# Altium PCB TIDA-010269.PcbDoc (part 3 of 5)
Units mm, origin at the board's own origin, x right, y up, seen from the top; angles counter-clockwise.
Board outline 87.61 x 53.51 mm, 8 copper layers (Top Layer, GND1, Signal 1, Power 1, Power 2, Signal 2, Layer 1, Bottom Layer), stack 1.645 mm thick; 482 components, 227 nets, 1562 pads, 953 vias.
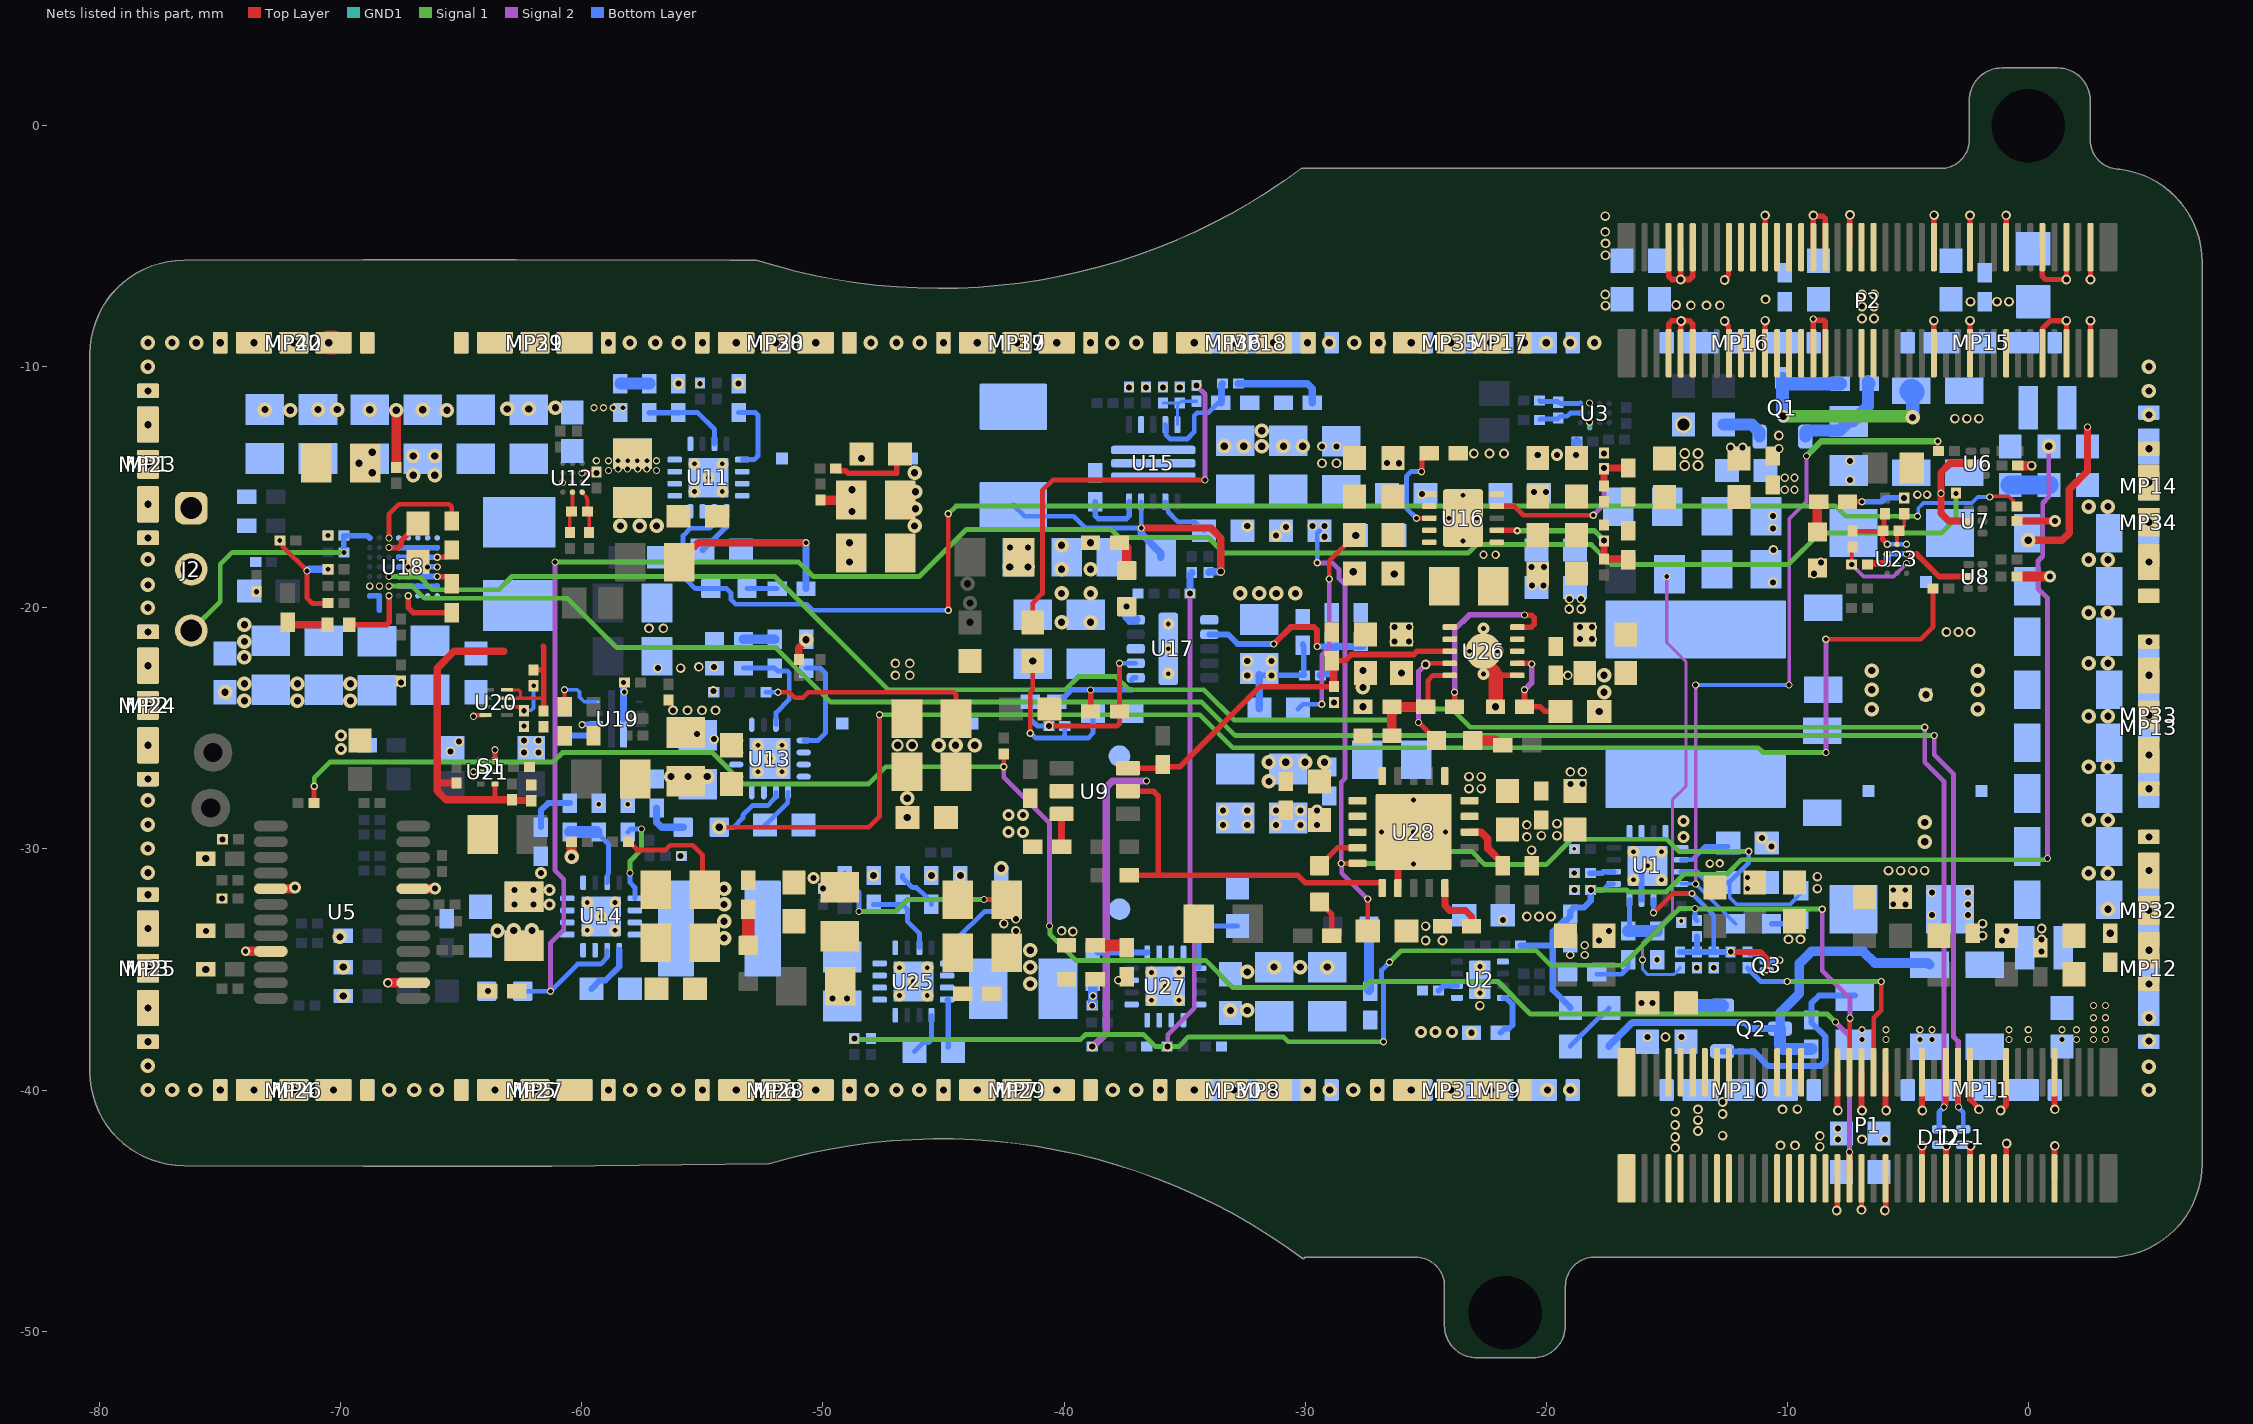
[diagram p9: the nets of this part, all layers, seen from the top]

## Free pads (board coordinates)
  round 0.5 hole 0.2: 3(-52.7,-26.8) 3(-52.7,-25.7) 3(-51.7,-26.8) 3(-51.7,-25.7)
  round 0.6 hole 0.3: 8(-67,-13.7) 8(-43.9,-20.6) 9(-66.1,-13.7) 9(-43.9,-19.8) 10(-69.25,-14) 10(-67,-14.5) 10(-44,-19) 11(-66.1,-14.5)
  round 0.4 hole 0.25: 11(-16.05,-36.4) 11(-15.8,-37.8) 11(-15.6,-36.4) 12(-15.05,-37.8)
  round 2.159 hole 3.048 unplated mask+0.127: MH2(-21.705,-49.233) MH2(0,0)

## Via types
v1: diameter 0.6, hole 0.3, Top Layer to Bottom Layer, tented both sides, 264 vias
v2: diameter 0.4, hole 0.25, Top Layer to Bottom Layer, tented both sides, 251 vias
v3: diameter 0.3, hole 0.2, Top Layer to Bottom Layer, tented both sides, 153 vias
v4: diameter 0.3, hole 0.2, Top Layer to Bottom Layer, 95 vias
v5: diameter 0.5, hole 0.25, Top Layer to Bottom Layer, tented both sides, 67 vias
v6: diameter 0.5, hole 0.2, Top Layer to Bottom Layer, 44 vias
v7: diameter 0.35, hole 0.22, Top Layer to Bottom Layer, tented both sides, 34 vias
v8: diameter 0.45, hole 0.3, Top Layer to Bottom Layer, tented both sides, 8 vias
v9: diameter 0.3, hole 0.15, Top Layer to Bottom Layer, tented both sides, 8 vias
v10: diameter 0.5, hole 0.3, Top Layer to Bottom Layer, tented both sides, 7 vias
v11: diameter 0.35, hole 0.25, Top Layer to Bottom Layer, tented both sides, 5 vias
v12: diameter 0.38, hole 0.25, Top Layer to Bottom Layer, tented both sides, 3 vias
v13: diameter 0.4, hole 0.22, Top Layer to Bottom Layer, tented both sides, 3 vias
v14: diameter 0.4, hole 0.25, Top Layer to Bottom Layer, 3 vias
v15: diameter 0.35, hole 0.2, Top Layer to Bottom Layer, tented both sides, 2 vias
v16: diameter 0.7, hole 0.5, Top Layer to Bottom Layer, tented both sides, 1 vias
v17: diameter 0.32, hole 0.21, Top Layer to Bottom Layer, tented both sides, 1 vias
v18: diameter 0.6, hole 0.3, Top Layer to Bottom Layer, 1 vias
v19: diameter 0.45, hole 0.25, Top Layer to Bottom Layer, tented both sides, 1 vias
v20: diameter 0.36, hole 0.25, Top Layer to Bottom Layer, tented both sides, 1 vias
v21: diameter 0.5, hole 0.25, Top Layer to Bottom Layer, 1 vias

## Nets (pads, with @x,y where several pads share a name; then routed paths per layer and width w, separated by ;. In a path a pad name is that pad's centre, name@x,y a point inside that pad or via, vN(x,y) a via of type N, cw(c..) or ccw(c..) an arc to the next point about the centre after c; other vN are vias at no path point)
1.8V_EN: R9.1 R166.1 R184.2 U9.6 U26.3 | length 16
  Top Layer w0.23: U9.6@-37.35,-26.65 -35.95,-26.65 -35.9,-26.6 -35.2,-26.6 -31.87,-23.27 R184.2@-28.8,-23.27 ; R166.1@-28.9,-22.2 -28.35,-22.2 -28.085,-21.935 -25.485,-21.935 -25.35,-21.8 U26.3@-24,-21.8
  Top Layer w0.3: R166.1@-28.81,-22.29 -28.81,-23.26 R184.2@-28.8,-23.27
1.15V_EN: R62.1 U9.5 U28.11 | length 15.5
  Top Layer w0.23: U9.5@-37.35,-27.6 -36.3,-27.6 -36.1,-27.8 -36.1,-31.1 ; R62.1@-37.3,-31.1 -36.1,-31.1 ; U28.11@-26.8,-31.625 -26.8,-31.44 -26.84,-31.4 -30,-31.4 -30.3,-31.1 -36.1,-31.1
1V2_DVDD: C204.1 L27.2 P1.19 P1.21
1V8_DVDD: C25.1 C183.1 L22.2 P1.47 P1.49 P1.68 P1.70 P2.51 P2.52 P2.53 P2.54 P2.55 P2.56 P2.59 P2.60 P2.61 P2.62
  other v2: -8.65,-42.35 -8.65,-41.9 -13.7,-41.7 -13.7,-41.25 -13.7,-40.8 -9.95,-33.75 -9.45,-33.75
  other v8: -14.25,-14.1 -13.7,-14.1 -14.25,-13.6 -13.7,-13.6
3.3V_AVDD: R138.1 R139.1 R143.1 R144.1 | length 4.7
  Top Layer w0.2: v3(-72.53,-17.2) -72.51,-17.2 -72.4,-17.31 -72.4,-17.465 v3(-71.4,-18.465) -71.4,-19.6 -71.181,-19.819 -70.549,-19.819 R143.1@-70.53,-19.8
  Bottom Layer w0.3: v3(-71.4,-18.465) -71.335,-18.4 v4(-70.53,-18.4)
+3.3V: C32.2 U2.6 | length 0.9
  Bottom Layer w0.24: C32.2@-24.47,-35.875 -24.45,-35.875 -24.25,-35.675 U2.6@-23.7,-35.675
+5.3V: C12.1 C98.1 C99.1 C100.1 C101.1 C201.1 R3.1 R10.1 R93.1 R95.2 R104.1 U1.3 U15.8@-36.3,-14.55 U28.10 | length 61.2
  Top Layer w0.2: R104.1@-41.3,-20.6 -41.3,-19.8 -40.9,-19.4 -40.9,-15.129 -40.471,-14.7 v3(-34.15,-14.7) ; v3(-28.5,-30.6) U28.10@-27.825,-30.6 ; C201.1@-27.4,-33.4 v3(-27.4,-32.082)
  Signal 2 w0.2: v2(-34.5,-10.77) -34.5,-10.8 -34.15,-11.15 v3(-34.15,-14.7) ; v3(-29.5,-18.13) -29.496,-18.134 -28.866,-18.134 -28.6,-18.4 -28.6,-18.778 -28.35,-19.028 -28.35,-27.083 -28.5,-27.233 v3(-28.5,-30.6) ; v3@-28.482,-30.618 -28.482,-31 v3(-27.4,-32.082)
  Signal 1 w0.2: v3(-28.5,-30.6) -26.7,-30.6 -26.2,-30.1 -23.09,-30.1 -22.54,-30.65 -20,-30.65 -18.95,-29.6 -15,-29.6 -14.5,-30.1 v3(-11.6,-30.1)
  Bottom Layer w0.152: v2(-34.5,-10.77) R95.2@-34.43,-10.7 ; C12.1@-12.45,-31.4 -12.387,-31.463 -12.387,-32.013 -12.1,-32.3 -9.89,-32.3 -9.42,-31.83 R10.1@-9.42,-31.73
  Bottom Layer w0.2: v3(-29.5,-18.13) -29.5,-16.9 C98.1@-29.4,-16.8 ; C12.1@-12.45,-31.4 -12.425,-31.4 -11.6,-30.575 v3(-11.6,-30.1)
  Bottom Layer w0.22: U1.3@-14.4,-30.95 -13.75,-30.95 -13.3,-31.4 C12.1@-12.45,-31.4
  other v2: -29.2,-17.05 -29.7,-16.6 -29.2,-16.6
AVDD_1P2: C191.1 L25.2 P2.39 P2.40 P2.41 P2.42
  other v2: -10.35,-13.4 -12.35,-13.35 -11.85,-13.35 -10.35,-12.85 -6.9,-8 -6.4,-8 -6.9,-7.5 -6.4,-7.5 -6.9,-7 -6.4,-7
DC_DC_CLK1: P1.43 R37.2 R111.1 | length 80.2
  Top Layer w0.2: R37.2@-71.12,-28.1 -71.11,-28.09 -71.11,-27.41 v3(-71.1,-27.4) ; v3(-42.5,-26.59) R111.1@-42.5,-26.06
  Top Layer w0.24: P1.43@-7.421,-43.664 v3(-7.421,-42.568)
  Signal 2 w0.2: v3(-42.5,-26.59) -42.5,-27.034 -40.6,-28.934 v3(-40.6,-33.2) ; v3(-8,-37.181) -7.421,-37.76 v3(-7.421,-42.568)
  Signal 1 w0.2: v3(-71.1,-27.4) -71.1,-27.05 -70.45,-26.4 -61.2,-26.4 -60.8,-26 -54.6,-26 -53.3,-27.3 -48.108,-27.3 -47.398,-26.59 v3(-42.5,-26.59) ; v3(-40.6,-33.2) -40.581,-33.219 -40.581,-33.556 -39.511,-34.625 -34.125,-34.625 -33,-35.75 -27.575,-35.75 -27.325,-35.5 -22,-35.5 -20.65,-36.85 -8.331,-36.85 v3(-8,-37.181)
DM_USB: D12.1 P1.28 U18.F3 | length 86.1
  Top Layer w0.23: v4(-3.5,-40.7) -3.5,-40.681 -3.428,-40.609 -3.428,-39.271 P1.28@-3.421,-39.264
  Signal 2 w0.2: v3(-4.3,-24.95) -4.3,-26.4 -3.5,-27.2 v4(-3.5,-40.7)
  Signal 1 w0.2: v3(-68,-18.7) -67.375,-18.7 -66.75,-18.7 -66.2,-19.25 -63.45,-19.25 -62.9,-18.7 -52,-18.7 -47.3,-23.4 -39.95,-23.4 -39.4,-22.85 -37.85,-22.85 -37.3,-23.4 -34.2,-23.4 -32.95,-24.65 -26.55,-24.65 -26.1,-24.2 -23.9,-24.2 -23.15,-24.95 v3(-4.3,-24.95)
  Bottom Layer w0.23: D12.1@-3.7,-41.625 -3.7,-40.919 -3.5,-40.719 v4(-3.5,-40.7)
DP_USB: D11.1 P1.26 U18.F2 | length 84.9
  Top Layer w0.23: v4@-2.921,-40.679 P1.26@-2.921,-39.264
  Signal 2 w0.2: v3(-3.9,-25.3) -3.9,-26.1 -3.1,-26.9 -3.1,-37.8 -2.9,-38
  Signal 2 w0.23: v4(-2.9,-40.7) -2.9,-38
  Signal 1 w0.2: v3(-68,-19.1) -67.034,-19.1 -66.534,-19.6 -60.6,-19.6 -58.55,-21.65 -51.95,-21.65 -49.7,-23.9 -34.3,-23.9 -32.9,-25.3 v3(-3.9,-25.3)
  Bottom Layer w0.2: v4(-2.9,-40.7) -2.9,-40.727 -2.7,-40.927 D11.1@-2.7,-41.625
  Bottom Layer w0.23: v4@-2.921,-40.679 v4(-2.9,-40.7)
FPGA_PG_1V: D5.2 R60.1 U13.14 | length 65
  Top Layer w0.2: v1(-54.3,-29.1) -48.1,-29.1 -47.657,-28.657 v3(-47.657,-24.432) ; v3(-8.4,-21.3) -4.463,-21.3 -3.96,-20.797 R60.1@-3.96,-19.2
  Signal 2 w0.2: v3(-8.4,-26) v3(-8.4,-21.3)
  Signal 1 w0.2: v3(-47.657,-24.432) -34.368,-24.432 -33,-25.8 -11.2,-25.8 -11,-26 v3(-8.4,-26)
  Bottom Layer w0.2: v1(-54.3,-29.1) -53.709,-29.1 -53.32,-28.711 -53.32,-28.591 -52.931,-28.202 -52.299,-28.202 -52.08,-27.983 -52.08,-27.971 -51.95,-27.841 U13.14@-51.95,-27.65
FPGA_PG_1V8: D6.2 R43.1 U14.14 | length 84.5
  Top Layer w0.2: v3(-3,-15.25) R43.1@-3,-15.23
  Signal 2 w0.2: v3(-61.3,-35.9) -61.3,-33.898 -60.75,-33.348 -60.75,-31.25 -61.119,-30.881 v3(-61.119,-18.1)
  Signal 1 w0.2: v3(-61.119,-18.1) -51.005,-18.1 -50.405,-18.7 -46,-18.7 -44.05,-16.75 -38.047,-16.75 -37.715,-17.082 -34.018,-17.082 -33.37,-17.73 -23.243,-17.73 -22.888,-17.375 -18.125,-17.375 -17.3,-18.2 -9.95,-18.2 -8.65,-16.9 -3.616,-16.9 -3,-16.284 v3(-3,-15.25)
  Bottom Layer w0.2: D6.2@-62.45,-35.9 v3(-61.3,-35.9) -60.177,-34.777 -59.227,-34.777 -58.95,-34.5 U14.14@-58.95,-34.2
FPGA_PG_2V5: D4.2 R54.1 U11.14 | length 64.9
  Top Layer w0.15: v3(-1.6,-15.4) -1.559,-15.4 -1.524,-15.365 -0.807,-15.365 -0.625,-15.547 -0.625,-15.665 -0.49,-15.8 R54.1@-0.47,-15.8
  Top Layer w0.2: v3(-44.8,-20.1) v3(-44.8,-16.1)
  Signal 1 w0.2: v3(-44.8,-16.1) -44.48,-15.78 -23.818,-15.78 -23.768,-15.83 -23.133,-15.83 -23.082,-15.78 -7.99,-15.78 -7.57,-16.2 v3(-4.6,-16.2)
  Bottom Layer w0.15: v3(-4.6,-16.2) -4.571,-16.171 -4.571,-15.874 -4.348,-15.65 -2.35,-15.65 -2.1,-15.4 v3(-1.6,-15.4)
  Bottom Layer w0.2: U11.14@-54.5,-16 -54.5,-16.5 -54.7,-16.7 -55.5,-16.7 -55.8,-17 -55.8,-18.7 -55.3,-19.2 D4.2@-54.65,-19.2 -54,-19.2 -53.813,-19.387 -53.813,-19.663 -53.625,-19.85 -50.672,-19.85 -50.422,-20.1 v3(-44.8,-20.1)
"GLOBAL ENABLE": P1.44 R8.1 R94.1 R110.1 R161.1 R173.1 | length 73.3
  Top Layer w0.2: P1.44@-7.421,-39.264 -7.41,-39.254 -7.41,-37.029 v3(-7.4,-37.019)
  Signal 2 w0.2: v2(-35.7,-38.2) -35.7,-37.7 -34.6,-36.6 -34.6,-32.964 -34.77,-32.794 v2(-34.77,-19.4) ; v3(-8.55,-32.5) -8.55,-35.05 -7.4,-36.2 v3(-7.4,-37.019)
  Signal 1 w0.2: v2(-48.7,-37.87) -48.67,-37.9 -39.31,-37.9 -39.11,-37.7 -36.7,-37.7 -36.2,-38.2 v2(-35.7,-38.2) -35.24,-38.2 -34.84,-37.8 -30.909,-37.8 -30.709,-38 v3(-26.75,-38) ; v2@-34.785,-19.415 v2(-34.77,-19.4) ; v3(-26.5,-34.7) -26.023,-34.223 -20.41,-34.223 -19.808,-34.825 -16.825,-34.825 -14.472,-32.472 v3(-13.822,-32.472) ; v3@-13.776,-32.472 -13.776,-32.486 -8.564,-32.486 v3(-8.55,-32.5)
  Bottom Layer w0.2: v3(-26.75,-38) -26.75,-35.467 -26.827,-35.391 -26.827,-35.027 v3(-26.5,-34.7) ; v3(-13.822,-32.472) -13.822,-32.898 R8.1@-13.75,-32.97
  Bottom Layer w0.3: v2(-34.77,-19.4) -34.77,-18.62 -34.7,-18.55 R94.1@-34.7,-18.53
GND: C13.2 C16.2 C17.1 C24.2 C25.2 C32.1 C33.2 C34.2 C39.2 C40.2 C41.2 C42.2 C43.2 C47.2 C50.2 C51.2 C52.2 C53.2 C54.2 C55.2 C57.2 C58.2 C59.2 C60.2 C61.2 C62.2 C63.2 C64.2 C65.2 C67.2 C68.2 C72.2 C73.2 C74.2 C75.2 C76.2 C77.2 C78.2 C79.2 C80.2 C81.2 C82.2 C83.1 C84.2 C85.2 C86.2 C87.2 C88.2 C90.2 C91.2 C92.2 C95.2 C96.2 C97.2 C98.2 C99.2 C100.2 C101.2 C102.2 C103.2 C104.2 C106.2 C107.2 C108.2 C109.2 C110.2 C113.2 C114.2 C115.1 C116.1 C117.2 C118.2 C119.1 C120.2 C121.2 C123.1 C125.2 C126.2 C127.2 C128.2 C129.2 C130.2 C131.2 C132.2 C133.2 C135.2 C136.2 C137.2 C138.2 C139.2 C140.2 C141.2 C142.2 C143.2 C144.2 C145.2 C146.2 C148.2 C149.1 C150.2 C151.2 C152.1 C153.1 C154.2 C155.2 C169.2 C172.2 C173.2 C174.2 C175.2 C176.2 C177.2 C178.2 C179.2 C180.2 C181.2 C182.2 C183.2 C184.2 C185.2 C186.2 C187.2 C190.2 C191.2 C192.2 C193.2 C194.2 C195.2 C196.2 C197.2 C198.2 C199.2 C200.2 C201.2 C202.2 C203.2 C204.2 C205.2 C206.2 C207.2 D8.1 D10.2 D11.2 D12.2 J2.2 L20.1 L21.1 L24.1 L28.1 L29.1 MP1.1 MP2.1 MP3.1 MP4.1 MP5.1 MP6.1 MP7.1 MP8.1 MP9.1 MP10.1 MP11.1 MP12.1 MP13.1 MP14.1 MP15.1 MP16.1 MP17.1 MP18.1 MP19.1 MP20.1 MP21.1 MP22.1 MP23.1 MP24.1 MP25.1 MP26.1 MP27.1 MP28.1 MP29.1 MP30.1 MP31.1 MP32.1 MP33.1 MP34.1 MP35.1 MP36.1 MP37.1 MP38.1 MP39.1 MP40.1 P1.9 P1.10 P1.17 P1.18 P1.23 P1.24 P1.27 P1.31 P1.32 P1.37 P1.38 P1.41 P1.42 P1.45 P1.46 P1.51 P1.52 P1.53 P1.54 P1.55 P1.56 P1.63 P1.64 P1.65 P1.66 P1.71 P1.72 P1.73 P1.74 P2.3 P2.4 P2.7 P2.8 P2.11 P2.12 P2.17 P2.18 P2.23 P2.24 P2.29 P2.30 P2.44 P2.47 P2.48 P2.49 P2.50 P2.57 P2.58 P2.63 P2.64 P2.69 P2.70 P2.71 P2.72 P2.73 P2.74 pad.3 pad.11@-15.6,-36.4 pad.11@-16.05,-36.4 R48.2 R49.2 R74.1 R75.2 R85.1 R86.2 R87.1 R88.2 R96.1 R97.1 R98.1 R100.1 R107.2 R126.2 R127.2 R129.1 R130.2 R132.1 R135.2 R137.1 R140.1 R141.1 R142.1 R151.2 R168.1 R169.2 R170.1 R180.1 R181.2 R182.1 R184.1 R185.1 R194.1 R195.1 S1.1 S1.3 U2.1 U2.5 U2.9 U3.C1 U3.C3 U5.5 U5.9 U5.14 U5.20 U6.2 U7.2 U8.2 U9.2 U11.3 U11.4 U11.5 U11.17@-54.75,-14.6 U12.B3 U12.C1 U13.3 U13.4 U13.5 U13.17 U14.3 U14.4 U14.5 U14.17@-59.2,-32.8 U15.2 U15.6@-36.3,-13.45 U16.4 U16.11 U17.6 U18.A4 U18.B4 U18.C4 U18.D4 U18.E4 U18.G2 U18.H2 U19.8 U20.4 U21.2 U21.6 U23.B3 U23.C1 U23.C3 U25.3 U25.4 U25.5 U25.17@-46.25,-35.5 U26.6 U26.11 U27.3 U27.4 U27.5 U27.17@-35.8,-35.7 U28.12 U28.21 | length 95.5
  Top Layer w0.102: C169.2@-18.5,-22.8 C169.2@-18.4,-22.7
  Top Layer w0.127: C61.2@-59.43,-14.4 -59.415,-14.385 C61.2@-59.4,-14.37
  Top Layer w0.18: v3(-64.5,-24.5) -64.45,-24.45 U20.4@-64,-24.45
  Top Layer w0.2: v3(-64.5,-26.8) U21.2@-64.2,-26.8 ; U21.6@-63.6,-26.3 v3(-63.6,-25.89) ; v1@-50.7,-21.36 v1(-50.7,-21.325) ; U28.21@-26.15,-29.95 v6(-25.5,-29.3)
  Top Layer w0.22: v2(-68.05,-35.555) v2@-68.047,-35.553 ; U5.14@-67.003,-35.553 U5.14@-67,-35.55 ; U12.B3@-59.99,-14.4 C61.2@-59.43,-14.4 ; v2(-12.6,-8.1) -12.6,-8.149 -12.436,-8.313 -12.436,-9.423 P2.63@-12.421,-9.438 ; v2(-12.6,-6.4) -12.6,-6.351 -12.436,-6.187 -12.436,-5.053 P2.64@-12.421,-5.038 ; P2.57@-10.921,-9.438 v2(-10.921,-8.088) ; P2.58@-10.921,-5.038 v2(-10.921,-3.721) v2@-10.9,-3.7 ; P2.50@-8.921,-5.038 v2(-8.921,-3.721) -8.886,-3.755 -8.515,-3.755 -8.421,-3.85 P2.48@-8.421,-5.038 ; v2(-7.95,-45) -7.921,-44.971 P1.45@-7.921,-43.664 ; P2.44@-7.421,-5.038 -7.408,-5.025 -7.408,-3.708 v2(-7.4,-3.7) ; v2@-6.95,-45 v2(-6.921,-44.971) P1.41@-6.921,-43.664 ; v2(-5.95,-45) -5.921,-44.971 P1.37@-5.921,-43.664 ; P1.32@-4.421,-39.264 P1.32@-4.41,-39.274 ; P2.29@-3.921,-9.438 v2(-3.921,-8.088) ; P2.30@-3.921,-5.038 -3.921,-3.721 v2@-3.9,-3.7 ; P1.24@-2.421,-39.264 -2.406,-39.279 -2.406,-40.406 -2.05,-40.762 v2(-2.05,-40.8) ; P2.23@-2.421,-9.438 v2(-2.421,-8.088) ; P2.24@-2.421,-5.038 v2(-2.421,-3.721) v2@-2.4,-3.7 ; P2.18@-0.921,-5.038 v2(-0.921,-3.721) v2@-0.9,-3.7 ; P2.12@0.579,-5.038 0.579,-6.25 0.708,-6.379 v2(1.579,-6.379) P2.8@1.579,-5.038 ; P2.7@1.579,-9.438 v2(1.579,-8.088) ; P2.3@2.579,-9.438 v2(2.579,-8.088) ; v2(2.579,-6.379) P2.4@2.579,-5.038
  Top Layer w0.23: -22.1,-22.8 U26.6@-21.2,-22.8 ; P2.73@-14.921,-9.438 -14.921,-8.235 -14.786,-8.1 -14.055,-8.1 -13.921,-8.235 P2.69@-13.921,-9.438 ; P2.74@-14.921,-5.038 -14.921,-6.245 -14.786,-6.379 v14(-14.421,-6.379) ; P2.71@-14.421,-9.438 -14.411,-9.428 v14@-14.411,-8.111 ; P2.72@-14.421,-5.038 v14(-14.421,-6.379) ; P2.70@-13.921,-5.038 -13.921,-6.245 -14.055,-6.379 v14(-14.421,-6.379) ; P2.49@-8.921,-9.438 v4(-8.921,-8.021) -8.829,-8.071 -8.485,-8.071 -8.421,-8.135 P2.47@-8.421,-9.438 ; U23.C1@-4.939,-17.765 -4.635,-17.765 -3.7,-18.7 U8.2@-2.5,-18.7 ; P2.11@0.579,-9.438 0.589,-9.428 0.589,-8.411 0.912,-8.088 v2(1.579,-8.088)
  Top Layer w0.24: P1.17@-0.921,-43.664 v2@-0.921,-42.321
  Top Layer w0.25: P1.46@-7.921,-39.264 -7.921,-40.829 v2(-7.9,-40.85) ; P1.42@-6.921,-39.264 -6.921,-40.829 v2(-6.9,-40.85) ; P1.38@-5.921,-39.264 -5.921,-40.829 v2(-5.9,-40.85) ; P1.31@-4.421,-43.664 v2@-4.421,-42.421 ; P1.32@-4.421,-39.274 -4.421,-40.829 v2(-4.4,-40.85) ; P1.27@-3.421,-43.664 v2@-3.421,-42.421 ; P1.23@-2.421,-43.664 v2@-2.421,-42.421 ; v2(-1.15,-40.85) -1.14,-40.85 -0.921,-40.631 P1.18@-0.921,-39.264 ; P1.9@1.079,-43.664 v2@1.079,-42.421 ; P1.10@1.079,-39.264 1.079,-40.779 v2(1.1,-40.8)
  Top Layer w0.3: R88.2@-51,-22.14 -51,-21.66 v1@-50.7,-21.36 ; C64.2@-48.8,-15.4 v1(-48.8,-15.1) ; U28.12@-26.15,-31.625 U28.21@-26.15,-29.95 ; C151.2@-6.67,-18.2 -6.635,-18.165 v3(-5.85,-18.165) ; U7.2@-2.5,-16.4 -3.3,-16.4 -3.623,-16.077 v3(-3.623,-15.25) -3.623,-14.385 -3.238,-14 U6.2@-2.4,-14 ; C54.2@-0.47,-16.4 v5(1.1,-16.4)
  Top Layer w0.4: v13(-73.95,-34.25) U5.9@-72.9,-34.25 ; U5.5@-72.9,-31.65 v5@-71.95,-31.65 ; v2@-68.047,-35.553 U5.14@-67.003,-35.553 ; R126.2@-67.7,-14.17 v1(-67.7,-11.8) ; U5.20@-67,-31.65 v5(-66.1,-31.65) ; v1(-60.43,-30.33) R85.1@-60.43,-29.7 ; R74.1@-50.1,-15.53 C64.2@-48.837,-15.53 ; U26.11@-22.6,-21.8 -22.6,-22.094 -22.1,-22.594 -22.1,-22.8 ; C55.2@-0.47,-18.7 v5(0.9,-18.7) ; C53.2@-0.44,-14.1 v2(0.14,-14.1)
  Top Layer w0.5: C184.2@-17.825,-24.3 v1(-17.8,-24.3)
  Top Layer w0.6: v1(-22.1,-24.1) -22.1,-22.8
  Top Layer w1: v1(-70.498,-9) MP40.1@-70.3,-9
  GND1 w0.23: -18.2,-12.536 v3(-18.2,-12.3)
  Bottom Layer w0.23: U18.E4@-67.6,-18.3 v4(-67.2,-18.3) v3(-66.8,-18.3) v3(-66.4,-18.3) v3(-66,-18.3) ; v3(-60,-24.85) -59.981,-24.85 -59.966,-24.835 -59.429,-24.835 U19.8@-59.419,-24.825 ; v3(-5.85,-17.765) v4(-5.05,-17.765)
  Bottom Layer w0.3: v7(-38.83,-36.5) R181.2@-38.815,-36.485 ; C198.2@-38.815,-35.515 C198.2@-38.8,-35.5 ; C34.2@-18.73,-13.1 -18.72,-13.11 C34.2@-18.715,-13.115 ; v3(-5.85,-18.165) v3(-5.85,-17.765)
  Bottom Layer w0.4: R181.2@-38.815,-36.485 C198.2@-38.815,-35.515 ; v5(-18.757,-13.663) -18.744,-13.65 -18.744,-13.11 -18.72,-13.11 C34.2@-18.715,-13.11
  other v1: -78,-40 -77,-40 -76.041,-40 -75,-40 -73.6,-40 -71.95,-40 -70.3,-40 -67.994,-40 -66.95,-40 -66.022,-40 -63.6,-40 -61.95,-40 -58.9,-40 -57.991,-40 -57.005,-40 -56,-40 -55,-40 -53.6,-40 -51.95,-40 -50.3,-40 -48.9,-40 -47.978,-40 -46.95,-40 -46,-40 -45,-40 -43.6,-40 -41.95,-40 -40.3,-40 -37.976,-40 -37.005,-40 -36,-40 -34.6,-40 -32.95,-40 -31.3,-40 -29.9,-40 -28.979,-40 -28,-40 -27,-40 -25.6,-40 -23.95,-40 -22.3,-40 -19.95,-40 -19,-40 5,-40 5,-39.026 -78,-39 -78,-38 5,-37.966 5,-37 -78,-36.6 -69.9,-36.1 5,-35.6 -32.4,-35.1 -75.6,-35 -78,-34.95 -69.9,-34.9 -31.286,-34.903 -30.2,-34.9 -29.086,-34.903 5,-34.2 -70.039,-33.65 3.4,-33.5 -78,-33.3 5,-32.55 -78,-31.9 -78,-30.984 5,-30.9 -42.6,-30.8 -75.6,-30.4 -78,-29.982 5,-29.5 -78,-28.99 -46.5,-28.7 -78,-27.989 -46.5,-27.9 5,-27.5 -78,-27.1 5,-26.1 -78,-25.7 5,-24.45 -27.6,-24.1 -78,-24.05 -74,-23.85 -71.8,-23.85 -69.6,-23.85 -74.8,-23.5 -17.6,-23.5 -27.6,-23.3 -74,-23.15 -71.8,-23.15 -69.6,-23.15 -17.6,-22.8 5,-22.8 -26,-22.7 -27.6,-22.6 -78,-22.4 5,-21.4 -78,-21 -40.1,-20.6 -38.9,-20.6 -78,-20 -40.1,-19.4 -38.9,-19.4 -32.7,-19.4 -31.9,-19.4 -31.2,-19.4 -30.4,-19.4 -78,-19.05 -26.3,-18.6 -28,-18.5 -40.1,-18.4 -38.9,-18.4 -48.9,-18.1 5,-18.1 -78,-17.991 -40.1,-17.4 -48.9,-17.3 -78,-17.1 5,-16.45 -48.8,-16 -78,-15.7 5,-14.8 -78,-14.05 -48.4,-13.8 5,-13.4 -33.35,-13.3 -32.55,-13.3 -31.8,-13.3 -30.9,-13.3 -30.1,-13.3 -31.8,-12.65 -78,-12.4 5,-12 -72.1,-11.8 -65.6,-11.8 -68.8,-11.784 -66.6,-11.784 -73.147,-11.773 -70.947,-11.773 -70.147,-11.773 -63.1,-11.75 -62.2,-11.75 -61.1,-11.7 -78,-11 5,-11.005 -78,-10 5,-10 -78,-9 -77,-9 -76,-9 -75,-9 -73.6,-9 -71.95,-9 -58.9,-9 -58.007,-9 -56.95,-9 -55.982,-9 -55,-9 -53.6,-9 -51.95,-9 -50.3,-9 -48.009,-9 -46.95,-9 -45.984,-9 -45,-9 -43.6,-9 -41.95,-9 -40.3,-9 -38.9,-9 -38.001,-9 -37.005,-9 -34.6,-9 -32.95,-9 -31.3,-9 -29.9,-9 -29,-9 -27.961,-9 -26.95,-9 -25.6,-9 -23.95,-9 -22.3,-9 -20.9,-9 -20,-9 -19,-9 -18,-9
  other v2: -14.65,-42.4 -4.402,-42.317 -3.402,-42.317 -2.402,-42.317 1.098,-42.317 -10.282,-42.296 -9.682,-42.296 -0.902,-42.217 -14.65,-41.95 -12.682,-41.896 -14.65,-41.45 -12.682,-40.996 -14.65,-40.9 -10.2,-40.8 -9.582,-40.796 -12.682,-40.496 -22.75,-36.5 0.55,-34.25 -25,-33.8 -24.3,-33.8 -17.8,-33.8 0.55,-33.75 -1.9,-33.6 -39.633,-33.426 -40.1,-33.4 -17.4,-33.4 0.55,-33.3 -25,-33.2 -1.9,-33.1 -74.93,-32.05 -50,-31.64 -8.75,-31.65 -8.75,-31.15 -20.6,-30.05 -74.9,-29.6 -20.8,-29.5 -20.2,-29.45 -19.55,-29.45 -20.8,-29 -19.55,-28.95 -62.4,-26 -61.8,-26 -65.45,-25.95 -65.1,-25.55 -62.4,-25.51 -61.8,-25.51 -54.518,-25.448 -55.218,-25.232 -56.218,-24.248 -55.618,-24.248 -55.018,-24.248 -54.459,-24.253 -28.8,-23.93 -54.548,-23.448 -67.5,-23.1 -19.1,-22.801 -56.85,-22.5 -55.9,-22.5 -55.15,-22.45 -54.518,-22.448 -57.218,-20.848 -56.618,-20.848 -20.583,-19.08 -20.11,-19.08 -8.9,-18.585 -20.6,-18.301 -20.1,-18.301 -8.604,-18.121 -29.3,-14.001 -28.7,-14.001 -26.6,-14 -26.1,-14.001 -23,-13.6 -22.35,-13.6 -21.75,-13.6 -29.3,-13.3 -28.7,-13.301 -37.3,-10.85 -36.6,-10.85 -35.9,-10.85 -35.2,-10.85 -17.543,-5.374 -17.543,-4.876 -17.55,-4.4 -17.55,-3.75 -3.91,-3.71
  other v3: -11.65,-31.64 -11.65,-31.19 -59.3,-28.15 -58.1,-28.15 -62.4,-24.9 -68.8,-19.1 -68.4,-19.1 -18.2,-11.5
  other v4: -70.53,-17 -60.8,-14.8 -60,-14.4 -58.9,-14.3 -56.9,-14.3 -58.496,-14.235 -58.104,-14.235 -57.682,-14.235 -57.308,-14.235 -59.4,-13.9 -58.9,-13.9 -58.5,-13.9 -58.1,-13.9 -57.7,-13.9 -57.3,-13.9 -56.9,-13.9 -59.5,-11.7 -59.1,-11.7 -58.7,-11.7 -58.3,-11.7
  other v5: -23.1,-37.625 -25.2,-37.6 -24.6,-37.6 -23.9,-37.6 -75.6,-33.4 -62.8,-32.3 -62,-32.3 -61.35,-32.3 -62.8,-31.7 -62,-31.7 -61.35,-31.7 -71.9,-31.6 -50.4,-31.2 -61.7,-31 -42.3,-29.3 -41.7,-29.3 -33.4,-29.001 -32.4,-29.001 -31.2,-29.001 -30.2,-29.001 -29.5,-29.001 -42.3,-28.6 -41.7,-28.6 -33.4,-28.401 -32.4,-28.401 -31.2,-28.401 -30.2,-28.401 -29.5,-28.4 -70,-25.85 -70,-25.3 -31.2,-17 -30.8,-16.65 -32.4,-16.6 -20.35,-13.65 -19.55,-13.65 -56,-10.7 -53.5,-10.7
  other v6: -36.375,-36.275 -35.225,-36.275 -46.825,-36.075 -45.675,-36.075 -22.75,-35.975 -35.8,-35.7 -46.25,-35.5 -36.375,-35.125 -35.225,-35.125 -46.825,-34.925 -45.675,-34.925 -22.75,-34.875 -59.775,-33.375 -58.625,-33.375 -59.2,-32.8 -59.775,-32.225 -58.625,-32.225 -25.5,-30.625 -26.825,-29.3 -24.175,-29.3 -25.5,-27.975 -52.2,-26.25 -22.6,-22.75 -23.175,-21.8 -22.025,-21.8 -22.6,-20.85 -23.45,-17.23 -24.025,-16.28 -22.875,-16.28 -23.45,-15.33 -55.325,-15.175 -54.175,-15.175 -54.75,-14.6 -55.325,-14.025 -54.175,-14.025
  other v7: -38.8,-36.1 -5.6,-32.3 -5.6,-31.7 -5.1,-31.7 -10.1,-15.1 -9.7,-15.1 -10.1,-14.6 -9.7,-14.6 -55.1,-10.7
  other v10: -47.9,-31.1 -45.5,-31.1 -44.3,-31.1 -46.9,-25.7 -46.3,-25.7 -38.9,-17.3
  other v11: -5.1,-32.3 -17.6,-13.6
  other v12: -55.9,-30.3
  other v13: -73.5,-19.33
  other v14: -59.4,-14.4 -14.4,-8.1
  other v16: -14.3,-12.4
"HV DISABLE": P1.40 R21.1 | length 9.7
  Top Layer w0.2: P1.40@-6.421,-39.264 -6.41,-39.254 -6.41,-37.01 -6.1,-36.7 v3(-6.1,-35.5)
  Signal 1 w0.2: v3(-10,-35.5) -8.455,-35.5 -8.454,-35.501 -6.955,-35.501 -6.954,-35.5 v3(-6.1,-35.5)
  Bottom Layer w0.2: R21.1@-11.65,-34.93 -11.65,-34.95 -11.1,-35.5 v3(-10,-35.5)
HV_PG: D3.2 R42.1 U1.4 | length 31
  Top Layer w0.152: v3(-3.761,-13.09) -3.761,-13.469 R42.1@-3.73,-13.5
  Signal 2 w0.152: v3(-13.8,-31.45) v3(-13.8,-23.2) ; v3(-9.924,-23.2) -9.924,-16.324 -9.2,-15.6 v3(-9.2,-13.7)
  Signal 1 w0.152: v3(-9.924,-23.2) v3@-9.912,-23.188
  Signal 1 w0.254: v3(-9.2,-13.7) -8.59,-13.09 v3(-3.761,-13.09)
  Bottom Layer w0.152: U1.4@-14.4,-31.45 v3(-13.8,-31.45) D3.2@-12.15,-33.1 ; v3(-13.8,-23.2) v3(-9.924,-23.2)
HVGND: C2.2 C3.2 C4.2 C5.2 C6.2 C7.2 C8.2 C9.2 C10.2 C11.2 C12.2 C14.2 C18.1 C19.1 C20.1 C21.1 C22.1 C23.1 C26.1 C27.1 C28.2 C29.2 C30.2 C31.2 C150.1 C152.2 C153.2 C154.1 C155.1 D2.1 L3.1 L20.2 L21.2 L24.2 L28.2 L29.2 Q3.2@-10.675,-34.625 R6.1 R11.1 R14.2 R15.1 R17.1 R18.1 R194.2 R195.2 U1.1 U1.7 U1.16 U1.17 | length 1.5
  Bottom Layer w0.24: U1.7@-16.05,-32.1 U1.17@-16.05,-30.95
  Bottom Layer w0.25: Q3.2@-10.675,-34.625 -10.675,-34.62 -10.32,-34.62 v17(-10.315,-34.615)
  other v1: 3.3,-32.5 2.5,-31 3.3,-31 2.5,-28.8 3.3,-28.8 2.5,-26.6 3.3,-26.6 2.5,-24.5 3.3,-24.5 -6.5,-24.2 -2.1,-24.2 -4.25,-23.6 -6.5,-23.4 -2.1,-23.4 -6.5,-22.6 -2.1,-22.6 2.5,-22.3 3.3,-22.3 2.5,-20.2 3.3,-20.2 2.5,-18 3.3,-18 2.5,-15.8 3.3,-15.8
  other v2: -7.9,-42.05 -6.9,-42.05 -5.95,-42.05 -7.9,-41.6 -21.8,-32.95 -4,-32.75 -2.5,-32.75 -2.5,-32.3 -4,-31.8 -2.5,-31.8 -18.83,-31.7 -19.05,-20.05 -18.55,-20.05 -19.041,-19.625 -18.549,-19.625 -10.6,-18.95 -10.579,-17.6 -10.6,-16.7 -10.6,-16.18 -7.4,-14.7 -7.4,-13.9 -3.05,-12.15 -2.55,-12.15 -2.05,-12.15 -17.543,-7.462 -14.607,-7.437 -14,-7.45 -13.35,-7.45 -12.8,-7.45 -2.4,-7.3 -1.3,-7.3 -0.8,-7.3 -10.9,-7.2 -17.55,-7
  other v3: -6.9,-37.9 -5.9,-37.9 -4.5,-37.9 -4,-37.9 -0.8,-37.9 0,-37.9 1.4,-37.9 2,-37.9 2.7,-37.9 3.2,-37.9 -6.9,-37.5 -5.9,-37.5 -4.5,-37.5 -4,-37.5 -0.8,-37.5 0,-37.5 1.4,-37.5 2,-37.5 2.7,-37.5 3.2,-37.5 2.7,-37 3.2,-37 2.7,-36.5 3.2,-36.5
  other v5: -10.65,-29.9 -11.05,-29.55 -14.3,-29.5 -14.3,-28.85
  other v6: -16.38,-31.28 -15.22,-31.28 -15.8,-30.7 -16.38,-30.12 -15.22,-30.12
  other v7: -13.75,-34.93 -13.05,-34.93 -15.4,-34.6 -19,-34.4 -18.4,-34.4 -18.4,-34 -18.83,-31
  other v9: -14.4,-32.99 -18.83,-30
MHV: C17.2 L6.2 P1.79 P1.80 pad.11@-15.8,-37.8 pad.12
  other v2: -14.382,-37.796
NetC1_1: C1.1 C15.1 L1.2 U1.13 U1.14
NetC1_2: C1.2 D1.2 L3.2
NetC2_1: C2.1 Q1.1 R1.2 | length 4.4
  Bottom Layer w0.254: C2.1@-7.45,-12.268 C2.1@-7.285,-12.268
  Bottom Layer w0.5: Q1.1@-9.25,-12.9 -9.25,-12.7 -9.2,-12.65 -7.832,-12.65 C2.1@-7.45,-12.268 ; C2.1@-7.285,-12.268 -6.65,-11.633 -6.65,-10.6 R1.2@-6.6,-10.7
NetC3_1: C3.1 C4.1 C5.1 L1.1 R2.2 R3.2 R5.2 | length 19.2
  Signal 2 w0.13: v3(-16,-34.6) -16,-33.899 -14.755,-32.654 -14.755,-29.703 -14.765,-29.693 -14.765,-27.965 -14.2,-27.4 -14.2,-22.239 -15,-21.439 v3(-15,-18.7)
  Bottom Layer w0.13: v3(-16,-34.6) -16,-35.004 -15.789,-35.215 -14.715,-35.215 -14.45,-34.95 R5.2@-14.45,-34.93
NetC6_1: C6.1 C7.1 C8.1 C9.1 D1.1 L2.1 R6.2 | length 6.5
  Top Layer w0.3: v1(0,-17.2) 1.4,-17.2 1.7,-16.9 1.7,-15.075 2.45,-14.325 v3(2.45,-12.5)
NetC10_1: C10.1 C11.1 L2.2 Q1.3 R1.1 R4.2 | length 10.5
  Signal 1 w0.5: v10(-10.163,-12.053) -4.918,-12.053 -4.89,-12.081 -4.819,-12.081 v18(-4.8,-12.1)
  Bottom Layer w0.55: Q1.3@-10.2,-10.675 -10.175,-10.7 R1.1@-7.8,-10.7 ; Q1.3@-10.2,-10.5 -10.2,-12.002 -10.163,-12.039 v10(-10.163,-12.053) ; v18(-4.8,-12.1) C11.1@-4.8,-11.05
  Bottom Layer w1: C11.1@-4.85,-11 C11.1@-4.8,-11.05
NetC14_1: C14.1 U1.2 | length 2.2
  Bottom Layer w0.2: U1.2@-14.4,-30.45 -13.95,-30.45 -13.4,-29.9 C14.1@-12.45,-29.9
NetC15_2: C15.2 D2.2 L5.2
NetC18_2: C18.2 C19.2 C20.2 C21.2 L5.1 L7.1 R14.1
NetC22_2: C22.2 C23.2 L7.2 Q2.3 R20.1 R23.1 | length 18.6
  Bottom Layer w0.3: R20.1@-17.4,-38.2 -17.4,-38.175 -16.425,-37.2 -16.399,-37.2 -11.75,-37.2 -11.5,-37.45 Q2.3@-10.3,-37.45
  Bottom Layer w0.4: Q2.3@-10.3,-37.45 -10.284,-37.434 -10.284,-36.784 -9.5,-36 -9.5,-34.75 -9,-34.25 -6.85,-34.25 -6.366,-34.734 -4.166,-34.734 C22.2@-4.1,-34.8
  Bottom Layer w0.5: Q2.3@-10.3,-37.45 -10.3,-38.151 -10.151,-38.3 R23.1@-9,-38.3
NetC24_1: C24.1 U9.3 | length 1.4
  Top Layer w0.3: C24.1@-40.1,-29.9 U9.3@-40.1,-28.55
NetC26_2: C26.2 Q3.3 R5.1 R8.2 R12.2 R15.2 U1.6 | length 10.1
  Top Layer w0.2: v4(-15.547,-32.647) -14.75,-31.85 v9(-13.95,-31.85)
  Top Layer w0.254: v7(-12.35,-34.27) -11.13,-34.27 -10.85,-34.55 v9(-10.85,-35.025)
  Bottom Layer w0.2: U1.6@-15.55,-32.1 -15.548,-32.102 v4(-15.547,-32.647) v4(-15.547,-32.647) ; v9(-13.95,-31.85) -13.05,-32.75 R15.2@-13.05,-34.27
  Bottom Layer w0.254: R5.1@-14.45,-34.27 C26.2@-13.75,-34.27 ; R8.2@-13.75,-33.63 C26.2@-13.75,-34.27 ; v7(-12.35,-34.27) R15.2@-13.05,-34.27 C26.2@-13.75,-34.27
NetC27_2: C27.2 U1.10 | length 1
  Bottom Layer w0.23: C27.2@-18.17,-31 -17.675,-31 -17.63,-30.955 -17.205,-30.955 U1.10@-17.2,-30.95
NetC28_1: C28.1 R19.2 U1.8 | length 2.4
  Bottom Layer w0.152: R19.2@-16.6,-33.25 R19.2@-16.55,-33.2
  Bottom Layer w0.2: R19.2@-16.55,-33.2 U1.8@-16.55,-32.1
  Bottom Layer w0.5: R19.2@-16.6,-33.4 C28.1@-15.4,-33.4
NetC29_1: C29.1 R19.1 | length 1.7
  Bottom Layer w0.2: C29.1@-17.9,-35.2 -16.875,-35.2 -16.6,-34.925 R19.1@-16.6,-34.6
NetC30_1: C30.1 R7.1 R11.2 R13.2 R25.1 U1.9 | length 45.3
  Signal 2 w0.2: v3(0.8,-30.4) 0.8,-19.6 0.4,-19.2 0.4,-18.05 0.6,-17.85 0.6,-15.65 0.85,-15.4 v1(0.85,-13.3)
  Signal 1 w0.2: v2@-18,-31.7 -16.667,-31.7 -16.587,-31.78 -15.013,-31.78 -14.283,-31.05 -12.5,-31.05 -11.9,-30.45 0.723,-30.45 0.773,-30.4 v3(0.8,-30.4)
  Bottom Layer w0.2: v2(-18.15,-31.7) -17.63,-31.7 -17.38,-31.45 U1.9@-17.2,-31.45
  Bottom Layer w0.254: R25.1@-21.07,-34 -19.737,-34 ; R13.2@-19,-36.6 -19,-36.575 -19.727,-35.848 -19.727,-34.01 -19.737,-34 ; R11.2@-19,-32.7 -19,-32.8 -19.173,-32.973 -19.273,-32.973 -19.737,-33.437 -19.737,-34 ; R11.2@-19,-32.6 -18.827,-32.427 -18.427,-32.427 -18.15,-32.15 v2(-18.15,-31.7)
NetC31_1: C31.1 Q2.1 R23.2 | length 9.2
  Bottom Layer w0.254: Q2.1@-12.7,-38.4 -11.4,-38.4 -10.8,-39 -8.608,-39 -8.423,-38.815 -8.423,-37.777 -9,-37.2 R23.2@-9,-37.1 -9,-36.4 -8.684,-36.084 C31.1@-7.2,-36.084
NetC33_1: C33.1 U2.4 | length 2
  Bottom Layer w0.152: U2.4@-21.8,-36.175 U2.4@-21.775,-36.2
  Bottom Layer w0.24: C33.1@-21.9,-37.625 -21.72,-37.445 -21.541,-37.445 -21.4,-37.304 -21.4,-36.45 -21.67,-36.18 U2.4@-21.775,-36.18
NetC35_1: C35.1 R31.1 U3.D2 | length 1.8
  Bottom Layer w0.2: R31.1@-20.27,-12.2 -20.235,-12.165 -19.535,-12.165 C35.1@-19.5,-12.13 -19.424,-12.054 -19.131,-12.054 -18.995,-11.919 U3.D2@-18.581,-11.919
NetC35_2: C35.2 R30.1 U3.D3 | length 1.7
  Bottom Layer w0.2: R30.1@-20.27,-11.4 -20.235,-11.435 -19.535,-11.435 C35.2@-19.5,-11.47 -19.391,-11.519 U3.D3@-18.581,-11.519
NetC56_1: C56.1 L10.1 U11.10 U11.11 U11.12
NetC56_2: C56.2 U11.13 | length 2
  Bottom Layer w0.23: C56.2@-55,-17.6 -54.975,-17.6 -54,-16.625 U11.13@-54,-16
NetC58_1: C58.1 C59.1 C60.1 R64.1 R67.2 U11.1 U11.2 U11.15 U11.16 | length 7.6
  Top Layer w0.3: R67.2@-55.968,-18.1 -55.968,-17.935 -55.483,-17.45 -55.318,-17.45 -55.168,-17.3 v4(-50.7,-17.3)
  Bottom Layer w0.3: R64.1@-50.7,-19.2 v4(-50.7,-17.3)
  other v1: -58.4,-16.6 -57.6,-16.6 -56.9,-16.6
NetC62_1: C62.1 U11.9 | length 3.3
  Bottom Layer w0.2: C62.1@-53.5,-11.9 -52.8,-11.9 -52.7,-12 -52.7,-13.7 -52.85,-13.85 U11.9@-53.35,-13.85
NetC63_1: C63.1 C64.1 C65.1 L10.2 L11.1 R68.2 | length 3.5
  Top Layer w0.23: R68.2@-49.47,-14.225 -49.375,-14.32 -49.055,-14.32 -48.95,-14.425 -46.935,-14.425 -46.935,-13.76 C65.1@-46.8,-13.625
  other v1: -4.3,-29.7 -4.3,-28.9 -46.2,-16.6 -46.165,-15.885 -46.165,-15.179 -46.2,-14.4
  other v2: -47,-22.8 -46.4,-22.8 -47,-22.3 -46.4,-22.3 -3.4,-21 -2.9,-21 -2.4,-21
NetC66_1: C66.1 R70.1 U12.D3 | length 1.8
  Top Layer w0.152: U12.D3@-59.99,-15.2 -59.99,-15.221 -59.8,-15.411 -59.8,-15.5 -59.77,-15.53 C66.1@-59.77,-16 -59.7,-16.07 R70.1@-59.7,-16.87
NetC66_2: C66.2 R71.1 U12.D2 | length 1.7
  Top Layer w0.152: R71.1@-60.5,-16.87 -60.5,-16.07 C66.2@-60.43,-16 -60.39,-15.96 U12.D2@-60.39,-15.2
NetC67_1: C67.1 R76.2 U11.7 | length 3.6
  Bottom Layer w0.2: C67.1@-56,-11.9 -55.2,-11.9 -54.5,-12.6 U11.7@-54.5,-13.2
  Bottom Layer w0.23: R76.2@-57.2,-11.9 C67.1@-56,-11.9
NetC68_1: C68.1 R76.1 | length 1.2
  Bottom Layer w0.5: C68.1@-58.4,-10.7 R76.1@-57.2,-10.7
NetC70_1: C70.1 L12.1 U13.10 U13.11 U13.12
NetC70_2: C70.2 U13.13 | length 1.8
  Bottom Layer w0.2: C70.2@-52.4,-29 -52.375,-29 -51.458,-28.083 -51.458,-27.658 U13.13@-51.45,-27.65
NetC71_1: C71.1 L14.1 U14.10 U14.11 U14.12
NetC71_2: C71.2 U14.13 | length 2.2
  Bottom Layer w0.254: C71.2@-59.6,-35.8 -59.252,-35.452 -59.021,-35.452 -58.45,-34.881 U14.13@-58.45,-34.2
NetC72_1: C72.1 C73.1 C74.1 R77.1 R81.2 U13.1 U13.2 U13.15 U13.16
  other v1: -56.3,-27 -55.6,-27 -54.8,-27
NetC75_1: C75.1 C76.1 C77.1 R78.1 R82.2 U14.1 U14.2 U14.15 U14.16
  other v1: -63.5,-33.4 -62.825,-33.381 -62.071,-33.381
NetC78_1: C78.1 U13.9 | length 4.4
  Bottom Layer w0.2: U13.9@-50.8,-25.5 -50.2,-25.5 -49.9,-25.2 -49.9,-22.7 -50.1,-22.5 C78.1@-50.7,-22.5
NetC79_1: C79.1 C84.1 C85.1 L12.2 L13.1 R84.2 | length 9.1
  Top Layer w0.2: v4(-51.87,-23.5) -51.396,-23.5 -51.166,-23.73 -50.834,-23.73 -50.604,-23.5 -44.578,-23.5 -44.484,-23.594 C79.1@-44.484,-24.6
  Bottom Layer w0.2: R84.2@-52.37,-23.5 v4(-51.87,-23.5)
  other v1: -45.2,-25.7 -44.5,-25.7 -43.7,-25.7
  other v2: -5.8,-30.9 -5.3,-30.9 -4.8,-30.9 -4.3,-30.9
NetC80_1: C80.1 U14.9 | length 3.8
  Top Layer w0.2: v4(-58,-31) v4@-57.981,-30.981
  Signal 1 w0.2: v4(-58,-31) -58,-30.5 -57.53,-30.03 v4(-57.53,-29.168)
  Bottom Layer w0.2: C80.1@-58.1,-29.3 -57.968,-29.168 v4(-57.53,-29.168) ; v4(-58,-31) -58,-31.4 -57.8,-31.6 U14.9@-57.8,-32.05
NetC81_1: C81.1 C82.1 C83.2 L14.2 L15.1 R83.2 | length 4.9
  Top Layer w0.2: R83.2@-58.07,-29.7 -58.05,-29.7 -57.71,-30.04 -56.524,-30.04 -56.334,-29.85 -55.395,-29.85 -55,-30.245 -55,-31.6 C82.1@-54.9,-31.7
  other v1: -54.1,-33.7 -54.1,-33 -54.1,-32.3 -54.1,-31.65
  other v2: -1.1,-33.8 -0.9,-33.4
NetC88_1: C88.1 R89.2 U14.7 | length 3.4
  Bottom Layer w0.2: C88.1@-59.3,-29.4 -58.897,-29.803 -58.897,-31.008 -58.93,-31.042 -58.93,-31.38 U14.7@-58.95,-31.4
  Bottom Layer w0.254: C88.1@-59.4,-29.3 C88.1@-59.3,-29.4
  Bottom Layer w0.5: R89.2@-60.5,-29.3 C88.1@-59.4,-29.3
NetC90_1: C90.1 R90.2 U13.7 | length 4.4
  Bottom Layer w0.2: C90.1@-53.3,-22.5 R90.2@-52,-22.5 -51.88,-22.62 -51.48,-22.62 -51.4,-22.7 -51.4,-23.8 -51.942,-24.342 -51.942,-24.842 U13.7@-51.95,-24.85
NetC91_1: C91.1 R89.1 | length 2
  Bottom Layer w0.25: C91.1@-61.7,-29.1 -61.7,-28.4 -61.4,-28.1 R89.1@-60.5,-28.1
NetC92_1: C92.1 R90.1 | length 1.3
  Bottom Layer w0.4: C92.1@-53.3,-21.3 R90.1@-52,-21.3
NetC94_1: C94.1 L16.2 U15.7@-36.3,-14
NetC94_2: C94.2 U15.13 | length 2.7
  Bottom Layer w0.22: C94.2@-38.7,-15.6 -38.7,-16.183 -38.583,-16.3 -37.417,-16.3 -37.3,-16.183 U15.13@-37.3,-15.6
NetC95_1: C95.1 C96.1 L16.1 R91.2 R92.1 U15.12 | length 13.7
  Top Layer w0.3: v4(-36.8,-16.682) -33.918,-16.682 -33.5,-17.1 v11@-33.5,-18.49
  Bottom Layer w0.2: L16.1@-42.1,-15.738 -41.638,-16.2 -39.6,-16.2 -39.118,-16.682 v4(-36.8,-16.682) U15.12@-36.8,-15.6
  Bottom Layer w0.3: v4(-36.8,-16.682) -36.8,-16.919 -35.984,-17.735 C95.1@-35.984,-17.9 ; R92.1@-34,-18.53 -33.97,-18.5 -33.49,-18.5 v11@-33.5,-18.49
  other v1: -42.25,-18.3 -41.5,-18.3
  other v2: -42.25,-17.5 -41.5,-17.5
  other v11: -33.5,-18.5
NetC97_1: C97.1 U15.10 | length 2.3
  Bottom Layer w0.2: U15.10@-35.8,-15.6 -35.775,-15.625 -35.775,-15.85 -35.675,-15.95 -35.675,-16.024 -35.274,-16.425 -34.575,-16.425 C97.1@-34.2,-16.8
NetC102_1: C102.1 C103.1 C111.1 L17.1 R101.2 R150.2 U16.10
  other v2: -20.5,-15.2 -20.013,-15.2
  other v15: -13.21,-30.609 -12.8,-30.6
NetC104_1: C104.1 R95.1 R98.2 U15.5 | length 2.4
  Bottom Layer w0.127: R98.2@-35.9,-11.5 C104.1@-35.2,-11.5 ; U15.5@-35.3,-12.4 -35.3,-11.6 C104.1@-35.2,-11.5 ; R95.1@-34.5,-11.43 -35.13,-11.43 C104.1@-35.2,-11.5
NetC106_1: C106.1 R99.2 U15.4 | length 4.6
  Bottom Layer w0.2: U15.4@-35.8,-12.4 -35.775,-12.425 -35.775,-12.825 -35.6,-13 -34.9,-13 -34.6,-12.7 -34.6,-12.027 -34.483,-11.91 -34.01,-11.91 -33.6,-11.5 C106.1@-33.5,-11.5
  Bottom Layer w0.3: C106.1@-33.5,-11.5 -33.465,-11.465 -33.465,-10.735 R99.2@-33.43,-10.7
NetC108_1: C108.1 R99.1 | length 3.8
  Bottom Layer w0.3: R99.1@-32.77,-10.7 -29.9,-10.7 -29.7,-10.9 C108.1@-29.7,-11.5
NetC109_1: C109.1 C110.1 R93.2 R150.1 U16.1 U16.2
  other v2: -25.15,-15.281
NetC111_2: C111.2 R100.2 R101.1 U16.9 | length 8
  Top Layer w0.2: U16.9@-22.05,-15.78 -21.32,-15.78 -20.941,-16.159 -18.055,-16.159 v3(-18.052,-16.162)
  Top Layer w0.3: R101.1@-17.6,-14.94 R100.2@-17.6,-14.254 ; R100.2@-17.585,-14.2 C111.2@-16.6,-14.2
  Signal 2 w0.2: v3(-18.052,-16.162) -17.6,-15.711 v2(-17.6,-14.2)
NetC112_1: C112.1 C115.2 C116.2 L18.1 R102.1 R152.2 U16.6 | length 0.1
  Signal 2 w0.2: v2(-20.3,-32.8) -20.3,-32.85 v2@-20.25,-32.9
  other v2: -20.8,-32.8 -19.8,-32.8
  other v7: -22.6,-17.8 -22.1,-17.8
NetC112_2: C112.2 R102.2 R103.1 U16.7 | length 6.7
  Top Layer w0.22: U16.7@-21.795,-16.8 -21.805,-16.79 -22.04,-16.79 U16.7@-22.05,-16.78 -21.242,-16.78 -21.222,-16.8 v9(-21.2,-16.8)
  Top Layer w0.3: v11(-17.6,-17.2) R103.1@-17.6,-17.97 -17.6,-17.975 -16.675,-17.975 -16.6,-17.9 C112.2@-16.6,-18
  Signal 1 w0.22: v9@-21.115,-16.8 -18,-16.8 v11(-17.6,-17.2)
NetC113_1: C113.1 C114.1 R113.2 R152.1 U16.5 | length 8.7
  Top Layer w0.2: v3(-29,-18.8) -29,-18.055 -27.945,-17 v1(-27.9,-17) ; C114.1@-27.95,-17 C114.1@-27.95,-16.98
  Signal 2 w0.2: v3(-29.31,-24) -29.31,-21.976 -29,-21.666 v3(-29,-18.8)
  Bottom Layer w0.2: R113.2@-30.3,-24.2 -30.1,-24 v3(-29.31,-24)
NetC118_1: C118.1 U16.3 | length 4.1
  Top Layer w0.2: v4(-25.38,-16.28) U16.3@-24.85,-16.28 ; v4(-25.176,-14.35) -25.176,-14.323 -25.15,-14.297 -25.15,-13.78 -24.95,-13.58 C118.1@-24.85,-13.58
  Bottom Layer w0.2: v4(-25.38,-16.28) -25.8,-15.86 -25.8,-14.54 -25.61,-14.35 v4(-25.176,-14.35)
NetC119_2: C119.2 R107.1 R109.2 U17.7 | length 9.2
  Top Layer w0.25: v4(-31.3,-21.5) -30.6,-20.8 -29.632,-20.8 -29.5,-20.932 v4(-29.5,-21.6)
  Bottom Layer w0.25: U17.7@-33.975,-21.1 -33.2,-21.1 -32.8,-21.5 v4(-31.3,-21.5) ; v4(-29.5,-21.6) R107.1@-28.8,-21.6
  Bottom Layer w0.3: R109.2@-29.37,-22.8 -29.31,-22.74 -28.976,-22.74 -28.8,-22.564 -28.8,-21.6 C119.2@-27.6,-21.6
NetC120_1: C120.1 C121.1 C122.1 R104.2 R105.2 R106.2 R108.2 U17.3 | length 7.3
  Top Layer w0.2: v4(-41.4,-25.2) -41.4,-23.5 -41.3,-23.4 v1(-41.3,-22.2)
  Bottom Layer w0.2: v4(-41.4,-25.2) -41.373,-25.2 -41.173,-25.4 -40.086,-25.4 ; R106.2@-39.97,-24.9 -39.97,-25.284 -40.086,-25.4 ; C122.1@-38.8,-24.3 -38.8,-25.2 -39,-25.4 -40.086,-25.4
NetC122_2: C122.2 C123.2 D8.2 D9.2 R109.1 R112.1 R113.1 U17.1 U17.11@-35.675,-21.7 | length 9.1
  Top Layer w0.23: R112.1@-38.9,-24.3 v3(-38.9,-23.403)
  Bottom Layer w0.23: D9.2@-40.3,-23.9 -40.2,-23.9 -39.7,-23.4 v3@-38.903,-23.4 ; v3(-38.9,-23.403) v3@-38.903,-23.4 ; -37.2,-23.4 v3@-38.903,-23.4 ; U17.1@-37.2,-22.985 -37.115,-22.9 U17.1@-37.025,-22.9 ; C123.2@-31.9,-22.765 -31.865,-22.8 R109.1@-30.03,-22.8 -30.065,-22.765 -30.065,-21.585 -30.082,-21.543 -30.1,-21.5 D8.2@-30.1,-21.55
  Bottom Layer w0.3: R113.1@-31.9,-24.2 C123.2@-31.9,-22.765
  other v5: -32.4,-22.8 -31.397,-22.8 -32.4,-22.2 -31.4,-22.2
  other v6: -35.675,-22.73 -35.675,-21.7 -35.675,-20.67
NetC124_1: C124.1 D9.1 R106.1 R112.2 U17.2 | length 8.4
  Top Layer w0.2: v2(-40.63,-24.9) v2@-40.6,-24.9 ; C124.1@-40.6,-24.2 v2@-40.6,-24.9 ; v4(-37.7,-22.3) R112.2@-37.7,-24.3 -37.7,-24.797 -37.802,-24.9 v2@-40.6,-24.9
  Bottom Layer w0.2: D9.1@-41.4,-23.9 -41.4,-24.6 -41.1,-24.9 v2(-40.63,-24.9) ; v4(-37.7,-22.3) U17.2@-37.025,-22.3
NetC125_1: C125.1 C126.1 R116.2 R117.1 R118.2 R145.2 U18.A1 U18.B1 U18.C1 U18.G1 U18.H1 | length 3.5
  Top Layer w0.23: R118.2@-7.6,-15.6 v3(-6.9,-15.6)
  Bottom Layer w0.22: U18.H1@-68.8,-19.5 U18.G1@-68.4,-19.5 -68.4,-20.1
  Bottom Layer w0.23: v3(-6.9,-15.6) -6.1,-15.6 -5.935,-15.435 v2(-5.15,-15.435)
  other v1: -74,-22.05 -74,-21.4 -74,-20.7
  other v7: -4.6,-15.3 -4.2,-15.3
NetC127_1: C127.1 C128.1 C129.1 C130.1 U18.A2 U18.B2 U18.C2 U18.D2 U18.E2 | length 1.6
  Bottom Layer w0.22: U18.E2@-67.6,-19.1 U18.D2@-67.2,-19.1 U18.C2@-66.8,-19.1 U18.B2@-66.4,-19.1 U18.A2@-66,-19.1
NetC134_1: C134.1 U18.D1 | length 2.4
  Top Layer w0.23: v4(-67.2,-19.5) -67.2,-20 -67,-20.2 C134.1@-65.4,-20.2
NetC134_2: C134.2 L19.2 U18.A3 U18.B3 U18.C3 U18.D3 U18.E3 | length 2.4
  Top Layer w0.23: v3(-66,-18.7) -65.987,-18.713 -65.687,-18.713 -65.685,-18.715 -65.585,-18.715 -65.4,-18.9 C134.2@-65.4,-19
  Bottom Layer w0.23: U18.E3@-67.6,-18.7 U18.D3@-67.2,-18.7 U18.C3@-66.8,-18.7 U18.B3@-66.4,-18.7 v3(-66,-18.7)
NetC135_1: C135.1 C139.1 C140.1 C141.1 C142.1 C143.1 C148.1 pad.8@-67,-13.7 pad.9@-66.1,-13.7 pad.10@-67,-14.5 pad.10@-69.25,-14 pad.11@-66.1,-14.5 R117.2 R121.2 R123.2 R124.1 R131.1 U18.A6 U18.B6 U18.C6 U18.D6 U18.E6 U19.5 U20.7 U20.8 U21.4 | length 22.4
  Top Layer w0.13: -63.277,-21.84 -63.237,-21.8 ; U20.8@-63.1,-23.4 -62.626,-23.4 -62.55,-23.476 -62.55,-23.747 -62.553,-23.75 -61.604,-23.75
  Top Layer w0.14: U20.7@-63.1,-23.75 -62.553,-23.75
  Top Layer w0.2: U21.4@-63.6,-27.3 -63.6,-27.95 -63.59,-27.96 ; R124.1@-62.9,-27.96 R124.1@-62.88,-27.98 ; C135.1@-62.12,-27.98 C135.1@-62.1,-28
  Top Layer w0.23: R131.1@-62,-22.57 -61.989,-22.559 -61.575,-22.559 ; C148.1@-61.6,-24.27 -61.575,-24.245 -61.575,-22.559 ; -61.6,-21.6 -61.575,-21.625 -61.575,-22.559
  Top Layer w0.3: R123.2@-65.2,-27.26 -65.993,-27.26 -66,-27.267 ; -63.237,-21.8 -65.3,-21.8 -66,-22.5 -66,-27.267 ; R124.1@-62.9,-27.96 -63.59,-27.96 -65.64,-27.96 -66,-27.6 -66,-27.267 ; R124.1@-62.88,-27.98 C135.1@-62.12,-27.98 ; R121.2@-58.3,-23.07 v4(-58.27,-23.1)
  Bottom Layer w0.23: U18.E6@-67.6,-17.5 U18.D6@-67.2,-17.5 U18.C6@-66.8,-17.5 U18.B6@-66.4,-17.5 U18.A6@-66,-17.5
  Bottom Layer w0.3: U19.5@-58.269,-24.6 v4(-58.27,-23.1)
  other v1: -68.7,-14.4 -68.7,-13.55
  other v4: -58.24,-23.484
NetC136_1: C136.1 U19.7 | length 1.3
  Bottom Layer w0.25: C136.1@-60.719,-25.3 U19.7@-59.419,-25.3
NetC137_1: C137.1 U19.10 | length 2.3
  Top Layer w0.15: C137.1@-60.719,-24.1 v4(-60.719,-23.4)
  Bottom Layer w0.15: v4(-60.719,-23.4) v4(-60.719,-23.4) -60.188,-23.401 -60.1,-23.489 -60.1,-23.7 -59.9,-23.9 U19.10@-59.419,-23.9
NetC138_1: C138.1 R131.2 U20.6 | length 2.1
  Top Layer w0.16: U20.6@-63.1,-24.1 -62.65,-24.1 C138.1@-62.5,-24.25
  Bottom Layer w0.16: v7@-62.5,-24.25 v7@-62.4,-24.25 ; v7(-62.4,-24.27) v7@-62.4,-24.25 ; v4(-62,-23.23) -62.013,-23.324 -62.013,-24.159 -62.104,-24.25 v7@-62.4,-24.25
NetC145_1: C145.1 C146.1 J2.1 R134.2 U18.A7 U18.B7 U18.C7 U18.D7 U18.E7
NetC147_1: C147.1 U18.F7 | length 4.4
  Top Layer w0.2: v4(-68,-17.1) -68,-16.1 -67.6,-15.7 -65.503,-15.7 -65.4,-15.803 C147.1@-65.4,-16.4
NetC147_2: C147.2 L19.1 U18.A5 U18.B5 U18.C5 U18.D5 U18.E5 | length 2.4
  Top Layer w0.23: v3(-66,-17.9) -65.992,-17.892 -65.692,-17.892 -65.685,-17.885 -65.585,-17.885 -65.393,-17.693 -65.393,-17.593 C147.2@-65.4,-17.6
  Bottom Layer w0.23: U18.E5@-67.6,-17.9 U18.D5@-67.2,-17.9 U18.C5@-66.8,-17.9 U18.B5@-66.4,-17.9 v3(-66,-17.9)
NetC149_2: C149.2 U18.F6 | length 1.7
  Top Layer w0.23: v4(-68,-17.5) -67.602,-17.5 -67.5,-17.397 -67.5,-17.225 -66.8,-16.525 C149.2@-66.8,-16.5
NetC151_1: C151.1 R147.2 U23.B1 | length 4.2
  Top Layer w0.15: v7(-7.33,-18.2) -7.33,-17.51 R147.2@-7.3,-17.48
  Signal 2 w0.15: v7@-7.4,-18.13 -6.83,-18.7 ; v7(-7.33,-18.2) -6.83,-18.7 ; v4(-5.05,-18.165) -5.585,-18.7 -6.83,-18.7
NetC157_1: C157.1 R146.1 R147.1 U23.D1 U23.D3 | length 3.6
  Top Layer w0.2: R147.1@-7.4,-16.84 -7.38,-16.82 C157.1@-6.05,-16.82 ; R146.1@-5.95,-16.095 -5.99,-16.135 -5.99,-16.76 C157.1@-6.03,-16.8 C157.1@-6.05,-16.82 ; v3(-5.85,-17.365) -6.05,-17.165 C157.1@-6.05,-16.82
  Bottom Layer w0.2: v3(-5.85,-17.365) v4(-5.05,-17.365)
NetC157_2: C157.2 R145.1 U23.D2 | length 1.4
  Top Layer w0.15: U23.D2@-5.45,-17.365 -5.45,-16.88 C157.2@-5.37,-16.8 -5.35,-16.8 -5.15,-16.6 R145.1@-5.15,-16.095
NetC169_1: C169.1 C180.1 C181.1 L22.1 R153.2 R167.2 U26.8 U26.9 U26.10 | length 7.8
  Top Layer w0.23: R167.2@-23.8,-24.1 v4(-23.8,-23.5) ; U26.10@-21.2,-20.8 -20.611,-20.8 -20.5,-20.689 -20.5,-20.411 -20.611,-20.3 v4(-20.9,-20.3) v4@-20.915,-20.285
  Signal 2 w0.23: v4(-23.8,-23.5) -23.8,-20.9 -23.185,-20.285 v4@-20.915,-20.285
  other v2: -18.6,-21.301 -18.1,-21.301 -18.6,-20.801 -18.1,-20.801
NetC171_1: C171.1 L23.1 U25.10 U25.11 U25.12 | length 2
  Bottom Layer w0.23: U25.12@-44.85,-36.25 -44.805,-36.25 -44.8,-36.255 C171.1@-44.8,-38.2
NetC171_2: C171.2 U25.13 | length 1.9
  Bottom Layer w0.2: C171.2@-46.2,-38.4 -45.825,-38.025 -45.603,-38.025 -45.5,-37.922 U25.13@-45.5,-36.9
NetC172_1: C172.1 C173.1 C177.1 C178.1 C179.1 L23.2 R153.1 R165.2 R166.2 U26.1 U26.2 | length 8.2
  Top Layer w0.2: v3(-43.319,-32.1) C177.1@-42.384,-32.1
  Signal 2 w0.2: v3(-48.5,-32.6) v3@-48.498,-32.598
  Signal 1 w0.2: v3(-48.5,-32.6) -47,-32.6 -46.5,-32.1 v3(-43.319,-32.1)
  Bottom Layer w0.2: R165.2@-49.1,-31 R165.2@-49.1,-31.1 -49.1,-31.2 -48.5,-31.8 v3(-48.5,-32.6)
  other v1: -41.4,-35.6 -41.4,-34.9 -41.4,-34.2
  other v2: -42,-33.4 -42.5,-33.1 -42,-32.9 -26.3,-21.4 -25.7,-21.4 -26.3,-20.8 -25.7,-20.8
NetC174_1: C174.1 C175.1 C176.1 R160.1 R162.1 R163.2 U25.1 U25.2 U25.16
  other v5: -49.6,-36.2 -49,-36.2
NetC182_1: C182.1 U25.9 | length 3.8
  Bottom Layer w0.2: U25.9@-44.85,-34.75 -44.67,-34.75 -44.4,-34.48 -44.4,-33.692 -43.308,-32.6 -42.8,-32.6 -42.6,-32.4 C182.1@-42.6,-32.3
NetC184_1: C184.1 R185.2 U26.7 | length 4.1
  Top Layer w0.23: U26.7@-21.2,-22.3 -21.195,-22.295 -20.613,-22.295 v4(-20.6,-22.33) ; v4(-20.9,-23.4) R185.2@-20.9,-24.1 -20.25,-24.1 -20.054,-24.296 -19.404,-24.296 C184.1@-19.4,-24.3
  Signal 2 w0.23: v4(-20.9,-23.4) -20.6,-23.1 v4(-20.6,-22.33)
NetC185_1: C185.1 R167.1 R170.2 U26.5 | length 4.7
  Top Layer w0.2: R167.1@-25,-24.1 -24.9,-24 -24.9,-23 -24.7,-22.8 U26.5@-24,-22.8
  Top Layer w0.4: C185.1@-26.4,-25.3 R170.2@-26.4,-24.1 R167.1@-25,-24.1
NetC186_1: C186.1 R171.2 U25.7 | length 3.3
  Bottom Layer w0.2: C186.1@-47.9,-32.3 R171.2@-46.7,-32.3 -46.5,-32.5 -46.5,-33 -46,-33.5 U25.7@-46,-34.1
NetC187_1: C187.1 R171.1 | length 1.8
  Bottom Layer w0.2: R171.1@-46.7,-31.1 -46.7,-31.2 -46.3,-31.6 -46.124,-31.6 -45.924,-31.8 -45.9,-31.8 -45.5,-32.2 C187.1@-45.5,-32.3
NetC189_1: C189.1 L26.1 U27.10 U27.11 U27.12
NetC189_2: C189.2 U27.13 | length 3.1
  Bottom Layer w0.2: U27.13@-34.4,-34.95 -34.4,-33.6 -34,-33.2 C189.2@-32.8,-33.2
NetC190_1: C190.1 C202.1 C203.1 L25.1 L27.1 R154.2 R179.2 U28.1 U28.18 U28.19 U28.20 | length 2.2
  Top Layer w0.3: U28.18@-23.175,-29.3 -23.17,-29.305 -22.695,-29.305 -22.425,-29.575 -22.425,-29.975 -21.8,-30.6 R179.2@-21.8,-30.7
  other v2: -23.2,-27.5 -22.7,-27.5 -19,-27.3 -18.5,-27.3 -23.2,-27 -22.7,-27 -19,-26.8 -18.5,-26.8
NetC192_1: C192.1 C193.1 C194.1 R172.1 R174.1 R175.2 U27.1 U27.2 U27.16
  other v1: -33.1,-36.7 -32.4,-36.7
NetC195_1: C195.1 C196.1 C197.1 C199.1 C200.1 L26.2 R154.1 R177.2 U28.5 U28.6 U28.7 U28.8 | length 12.8
  Signal 2 w0.3: v2@-38.8,-38.2 -38.25,-37.65 -38.25,-27.45 -37.985,-27.185 v3(-36.574,-27.185)
  other v1: -31.5,-27.2 -31.5,-26.4 -30.8,-26.4 -30,-26.4 -29.2,-26.4
  other v2: -38.83,-38.2
NetC198_1: C198.1 U27.9 | length 2.1
  Bottom Layer w0.254: C198.1@-38.6,-34.3 U27.9@-36.55,-34.3
NetC205_1: C205.1 U28.15 | length 2.4
  Top Layer w0.3: U28.15@-24.2,-31.625 -24.2,-32.35 -24,-32.55 -23.35,-32.55 -23.1,-32.8 C205.1@-23.1,-33.2
NetC206_1: C206.1 R183.2 U27.7 | length 0.5
  Bottom Layer w0.22: v7(-37.75,-35.45) U27.7@-37.2,-35.45
NetC207_1: C207.1 R183.1 | length 1.3
  Top Layer w0.16: R183.1@-37.5,-34 R183.1@-37.4,-34.1
  Top Layer w0.5: C207.1@-38.7,-34 R183.1@-37.5,-34
NetD3_1: D3.1 R10.2 | length 1.4
  Bottom Layer w0.23: D3.1@-10.65,-33.1 -9.6,-33.1 -9.4,-32.9 R10.2@-9.42,-32.93
NetD4_1: D4.1 R64.2 | length 1.2
  Bottom Layer w0.2: D4.1@-53.15,-19.2 R64.2@-51.9,-19.2
NetD5_1: D5.1 R77.2 | length 1.8
  Bottom Layer w0.3: R77.2@-56.9,-28.3 -56.9,-28.9 -56.7,-29.1 D5.1@-55.8,-29.1
NetD6_1: D6.1 R78.2
  other v21: -63.9,-35.9
NetD7_1: D7.1 R160.2 | length 1.5
  Top Layer w0.5: D7.1@-53.1,-34 R160.2@-53.1,-32.5
NetD10_1: D10.1 R118.1 | length 1.3
  Top Layer w0.4: R118.1@-8.85,-15.6 -8.75,-15.7 D10.1@-8.75,-16.85
NetD13_1: D13.1 U18.F1 | length 2.8
  Top Layer w0.23: D13.1@-69.65,-20.7 -68.103,-20.7 -68,-20.597 v4(-68,-19.5)
NetD13_2: D13.2 R133.1 | length 1.6
  Top Layer w0.3: R133.1@-72.1,-20.7 D13.2@-70.55,-20.7
NetD14_1: D14.1 R172.2 | length 2.7
  Bottom Layer w0.2: R172.2@-27.35,-35.85 R172.2@-27.3,-35.9
  Bottom Layer w0.4: R172.2@-27.35,-35.85 D14.1@-27.35,-33.2
NetD15_1: D15.1 R176.1 | length 1.6
  Top Layer w0.22: D15.1@-29.4,-32.2 -28.9,-32.7 R176.1@-28.9,-33.6
NetD15_2: D15.2 U28.9 | length 1.9
  Top Layer w0.22: D15.2@-29.4,-30.7 -28.65,-29.95 U28.9@-27.825,-29.95
NetD16_1: D16.1 R164.1 | length 1.3
  Top Layer w0.4: D16.1@-23.05,-25.5 -22.1,-25.5 -21.9,-25.7 R164.1@-21.8,-25.7
NetD16_2: D16.2 U26.4 | length 4.6
  Top Layer w0.2: v4(-25.297,-24.753) D16.2@-24.55,-25.5 ; v2(-25,-22.347) -25,-22.3 U26.4@-24,-22.3
  Signal 2 w0.2: v4(-25.297,-24.753) -25.297,-22.644 v2(-25,-22.347)
NetD17_1: D17.1 R151.1 | length 1.3
  Top Layer w0.4: R151.1@-37.7,-17.3 -37.6,-17.3 -37.4,-17.5 D17.1@-37.4,-18.45
NetD17_2: D17.2 U17.5 | length 0.8
  Bottom Layer w0.4: v2(-37.4,-19.95) -37.4,-20.339 -37.239,-20.5 U17.5@-37.025,-20.5
NetJ2_3: J2.3 R136.1 R137.2 U18.H7 | length 10.4
  Signal 2 w0.2: v4@-69.885,-17.715 v4(-69.87,-17.7)
  Signal 1 w0.2: J2.3@-76.2,-20.94 -75,-19.74 -75,-18.2 -74.5,-17.7 v4(-69.87,-17.7)
  Bottom Layer w0.23: v4(-69.87,-17.7) R137.2@-69.87,-17 -68.9,-17 U18.H7@-68.8,-17.1
NetL4_1: L4.1 Q1.2 | length 1.8
  Bottom Layer w0.5: L4.1@-12.65,-12.4 -11.462,-12.4 -11.15,-12.712 Q1.2@-11.15,-12.9
NetL6_1: L6.1 Q2.2 | length 1.5
  Bottom Layer w0.152: L6.1@-14.2,-36.4 L6.1@-14.1,-36.3
  Bottom Layer w0.55: L6.1@-14.1,-36.5 Q2.2@-12.7,-36.5
NetQ3_1: Q3.1@-11.025,-34.625 R21.2 | length 0.8
  Bottom Layer w0.2: R21.2@-11.65,-34.27 -11.56,-34.36 -11.24,-34.36 -11.025,-34.575 Q3.1@-11.025,-34.625
NetR4_1: R4.1 R7.2 | length 1.7
  Bottom Layer w0.24: R7.2@0.85,-14.9 R7.2@0.9,-14.95
  Bottom Layer w0.8: R4.1@-0.75,-14.9 R7.2@0.85,-14.9
NetR13_1: R13.1 R20.2 | length 2.3
  Bottom Layer w0.2: R13.1@-19,-38.2 -19,-38.175 -17.825,-37 -17.775,-37 -17.4,-36.625 R20.2@-17.4,-36.6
